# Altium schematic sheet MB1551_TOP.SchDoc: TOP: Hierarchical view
size A3; Date: Not used; ApprovedBy: Not used; CheckedBy: Not used; Author: Not used; CompanyName: STMicroelectronics; DrawnBy: Not used; Engineer: Not used; Organization: Not used; Address1: Not used; Address2: Not used; Address3: Not used; Address4: Not used; DocumentNumber: 2; Revision: Not used; SheetNumber: 2; SheetTotal: 16
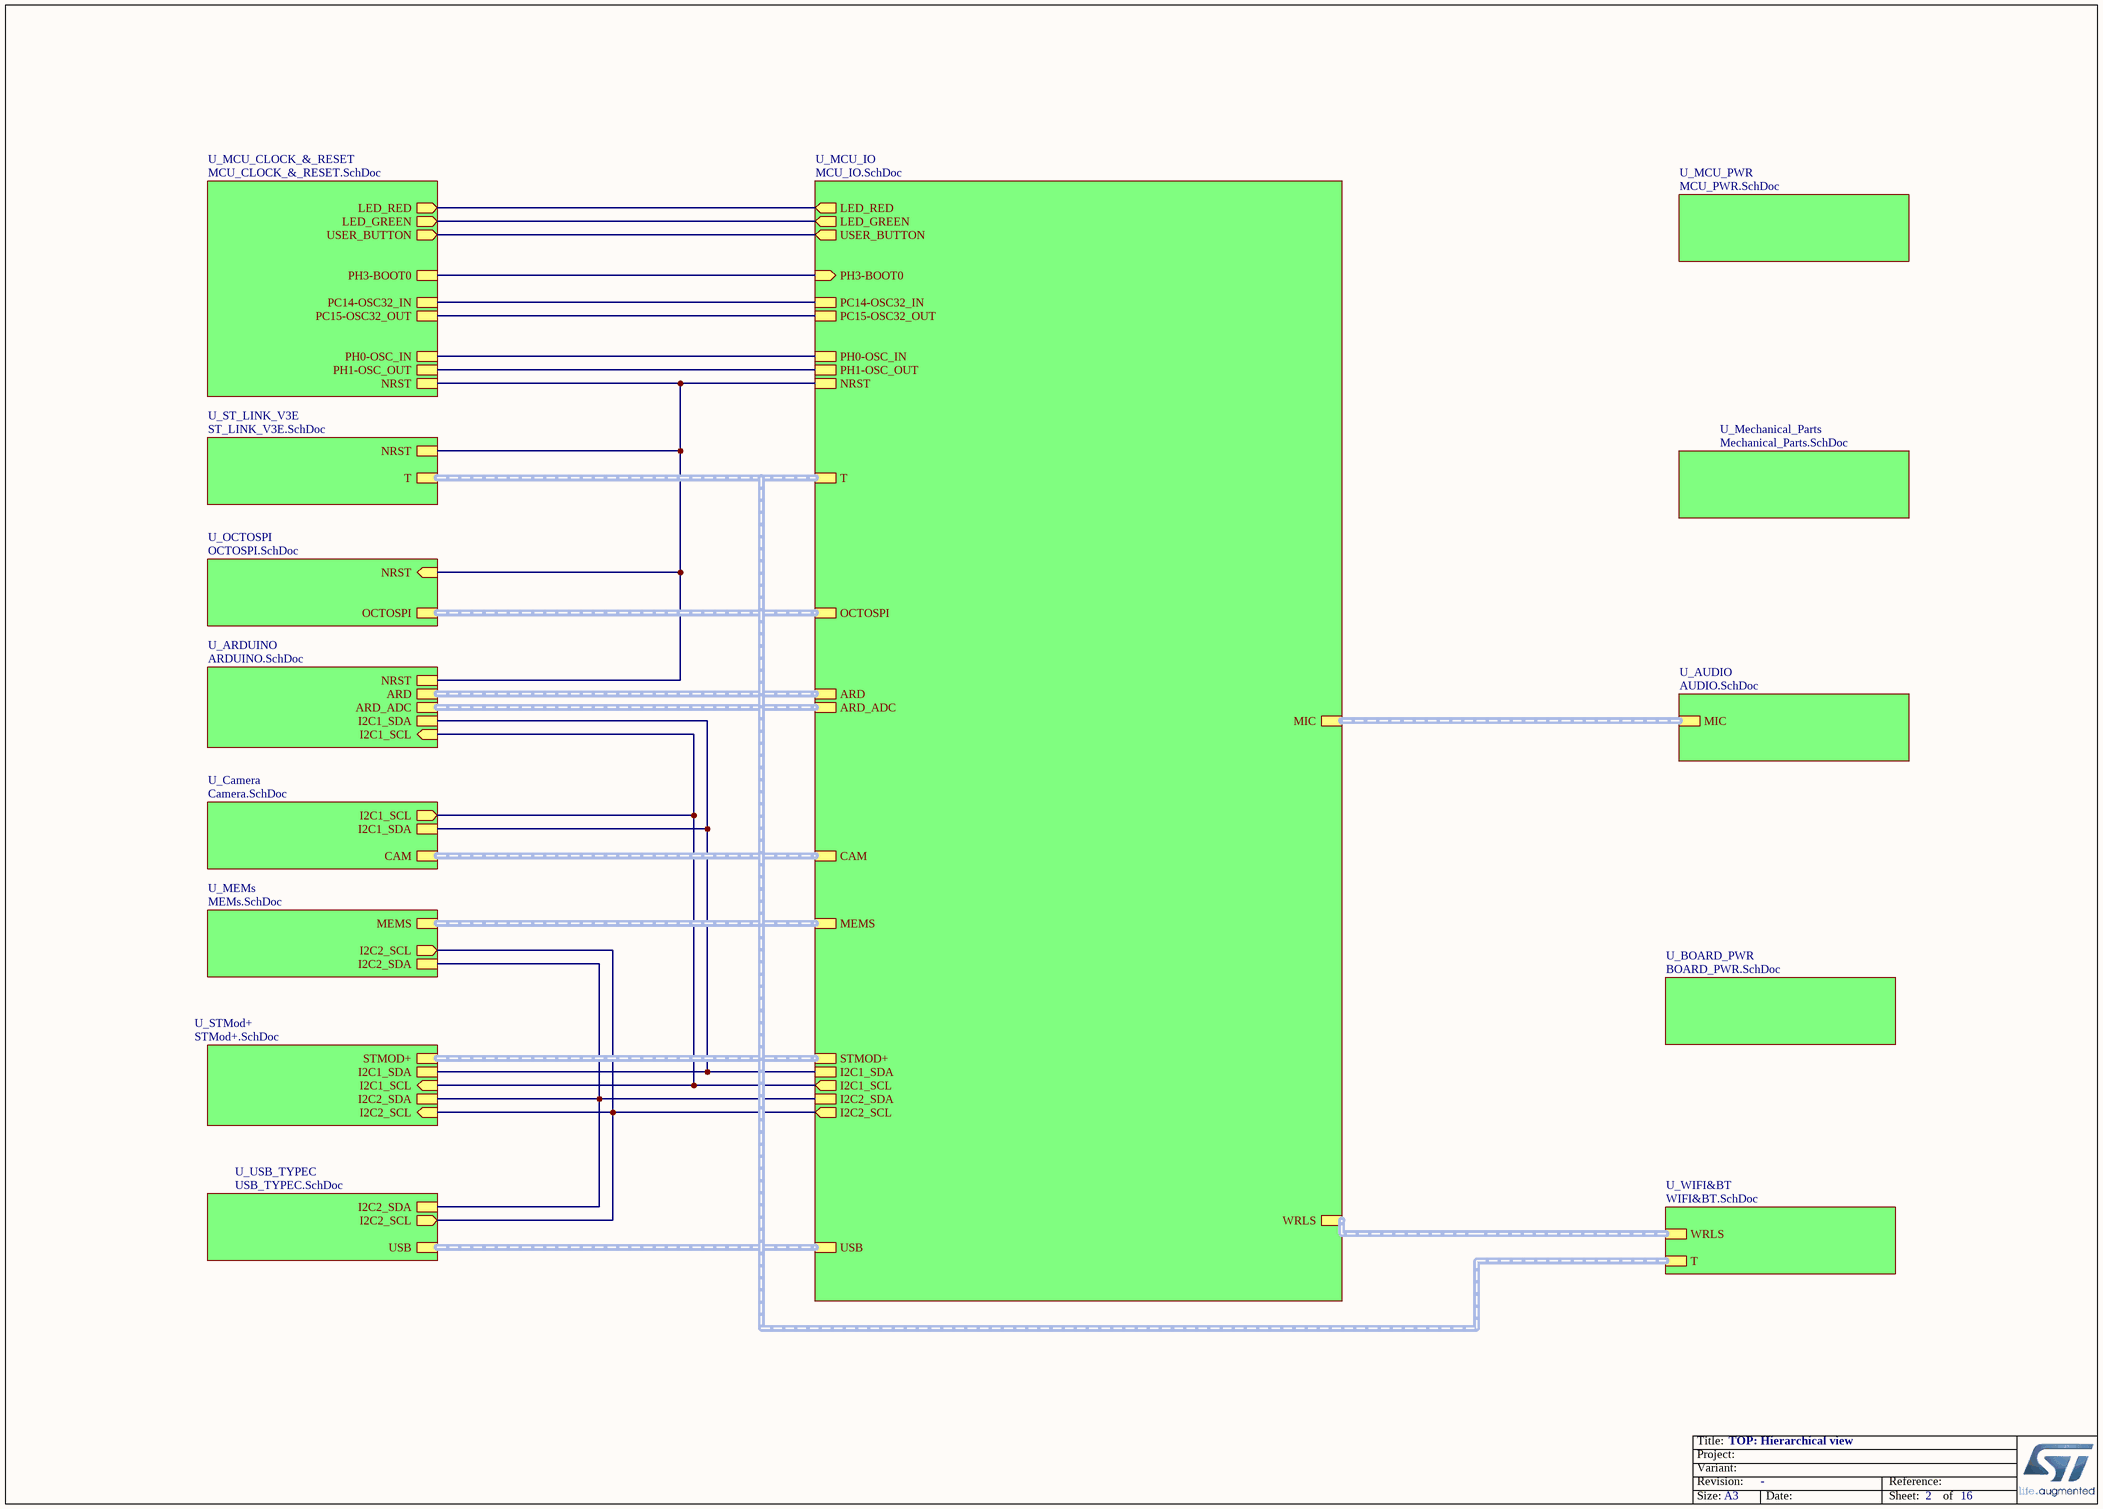
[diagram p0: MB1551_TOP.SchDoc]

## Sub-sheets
U_ARDUINO = ARDUINO.SchDoc: NRST, I2C1_SDA, I2C1_SCL (in), ARD_ADC (harness ARD_ADC), ARD (harness ARD)
U_AUDIO = AUDIO.SchDoc: MIC (harness MIC)
U_BOARD_PWR = BOARD_PWR.SchDoc: no entries
U_Camera = Camera.SchDoc: I2C1_SCL (out), I2C1_SDA, CAM (harness CAM)
U_MCU_CLOCK_&_RESET = MCU_CLOCK_&_RESET.SchDoc: NRST, PH3-BOOT0, PC14-OSC32_IN, PC15-OSC32_OUT, LED_RED (out), LED_GREEN (out), PH0-OSC_IN, PH1-OSC_OUT, USER_BUTTON (out)
U_MCU_IO = MCU_IO.SchDoc: PH3-BOOT0 (in), NRST, PH0-OSC_IN, PH1-OSC_OUT, PC14-OSC32_IN, PC15-OSC32_OUT, LED_RED (out), LED_GREEN (out), USER_BUTTON (out), OCTOSPI (harness OCTOSPI), STMOD+ (harness STMOD+), ARD_ADC (harness ARD_ADC), ARD (harness ARD), USB (harness USB), CAM (harness CAM), MIC (harness MIC), MEMS (harness Mems), WRLS (harness WRLS), T (harness T), I2C1_SDA, I2C1_SCL (out), I2C2_SDA, I2C2_SCL (out)
U_MCU_PWR = MCU_PWR.SchDoc: no entries
U_Mechanical_Parts = Mechanical_Parts.SchDoc: no entries
U_MEMs = MEMs.SchDoc: I2C2_SDA, I2C2_SCL (out), MEMS (harness Mems)
U_OCTOSPI = OCTOSPI.SchDoc: NRST (in), OCTOSPI (harness OCTOSPI)
U_ST_LINK_V3E = ST_LINK_V3E.SchDoc: NRST, T (harness T)
U_STMod+ = STMod+.SchDoc: STMOD+ (harness STMOD+), I2C1_SDA, I2C1_SCL (in), I2C2_SDA, I2C2_SCL (in)
U_USB_TYPEC = USB_TYPEC.SchDoc: USB (harness USB), I2C2_SDA, I2C2_SCL (out)
U_WIFI&BT = WIFI&BT.SchDoc: WRLS (harness WRLS), T (harness T)

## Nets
(unnamed): sheet U_ARDUINO/NRST, sheet U_MCU_CLOCK_&_RESET/NRST, sheet U_MCU_IO/NRST, sheet U_OCTOSPI/NRST, sheet U_ST_LINK_V3E/NRST
(unnamed): sheet U_ARDUINO/I2C1_SDA, sheet U_Camera/I2C1_SDA, sheet U_MCU_IO/I2C1_SDA, sheet U_STMod+/I2C1_SDA  [a separate net that carries the same name]
(unnamed): sheet U_ARDUINO/I2C1_SCL, sheet U_Camera/I2C1_SCL, sheet U_MCU_IO/I2C1_SCL, sheet U_STMod+/I2C1_SCL  [a separate net that carries the same name]
(unnamed): sheet U_MCU_CLOCK_&_RESET/PH3-BOOT0, sheet U_MCU_IO/PH3-BOOT0  [a separate net that carries the same name]
(unnamed): sheet U_MCU_CLOCK_&_RESET/PC14-OSC32_IN, sheet U_MCU_IO/PC14-OSC32_IN  [a separate net that carries the same name]
(unnamed): sheet U_MCU_CLOCK_&_RESET/PC15-OSC32_OUT, sheet U_MCU_IO/PC15-OSC32_OUT  [a separate net that carries the same name]
(unnamed): sheet U_MCU_CLOCK_&_RESET/LED_RED, sheet U_MCU_IO/LED_RED  [a separate net that carries the same name]
(unnamed): sheet U_MCU_CLOCK_&_RESET/LED_GREEN, sheet U_MCU_IO/LED_GREEN  [a separate net that carries the same name]
(unnamed): sheet U_MCU_CLOCK_&_RESET/PH0-OSC_IN, sheet U_MCU_IO/PH0-OSC_IN  [a separate net that carries the same name]
(unnamed): sheet U_MCU_CLOCK_&_RESET/PH1-OSC_OUT, sheet U_MCU_IO/PH1-OSC_OUT  [a separate net that carries the same name]
(unnamed): sheet U_MCU_CLOCK_&_RESET/USER_BUTTON, sheet U_MCU_IO/USER_BUTTON  [a separate net that carries the same name]
(unnamed): sheet U_MCU_IO/I2C2_SDA, sheet U_MEMs/I2C2_SDA, sheet U_STMod+/I2C2_SDA, sheet U_USB_TYPEC/I2C2_SDA  [a separate net that carries the same name]
(unnamed): sheet U_MCU_IO/I2C2_SCL, sheet U_MEMs/I2C2_SCL, sheet U_STMod+/I2C2_SCL, sheet U_USB_TYPEC/I2C2_SCL  [a separate net that carries the same name]

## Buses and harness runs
harness sheet U_ARDUINO/ARD = sheet U_MCU_IO/ARD
harness sheet U_ARDUINO/ARD_ADC = sheet U_MCU_IO/ARD_ADC
harness sheet U_AUDIO/MIC = sheet U_MCU_IO/MIC
harness sheet U_Camera/CAM = sheet U_MCU_IO/CAM
harness sheet U_MCU_IO/MEMS = sheet U_MEMs/MEMS
harness sheet U_MCU_IO/OCTOSPI = sheet U_OCTOSPI/OCTOSPI
harness sheet U_MCU_IO/STMOD+ = sheet U_STMod+/STMOD+
harness sheet U_MCU_IO/T = sheet U_ST_LINK_V3E/T = sheet U_WIFI&BT/T
harness sheet U_MCU_IO/USB = sheet U_USB_TYPEC/USB
harness sheet U_MCU_IO/WRLS = sheet U_WIFI&BT/WRLS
